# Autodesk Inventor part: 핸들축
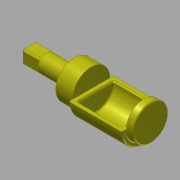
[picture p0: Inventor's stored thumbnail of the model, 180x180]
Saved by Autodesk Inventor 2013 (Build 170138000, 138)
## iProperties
Created: 2018-01
Part Number: 핸들축
Material: 강철, 연강
Document SubType Name: Modeling
Designer: mduedu
Density: 1 g/cm^3
Author: mduedu
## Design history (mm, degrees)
sketch "스케치1"
  geometry: L1 (0, 0)-(-38, 0); L2 (-38, 0)-(-38, -7.5); L3 (-38, -7.5)-(0, -7.5); L4 (0, -7.5)-(0, 0); L5 (-38, 0)-(-53, 0); L6 (-53, 0)-(-53, -16); L7 (-53, -16)-(-38, -16); L8 (-38, -16)-(-38, 0); L9 (-53, 0)-(-98, 0); L10 (-98, 0)-(-98, -19); L11 (-98, -19)-(-53, -19); L12 (-53, -19)-(-53, 0); L13 (-98, 0)-(-104, 0); L14 (-104, 0)-(-104, -15); L15 (-104, -15)-(-98, -15); L16 (-98, -15)-(-98, 0)
  constraints: 32 end point, 8 parallel, 4 horizontal, 4 perpendicular
  dimensions: "d0" = 6 distance of L14.end L15.end; "d2" = 30 diameter of L15 L13; "d3" = 32 diameter of L7 L5; "d4" = 15 distance of L6.end L7.end; "d5" = 45 distance of L10.end L11.end; "d6" = 38 diameter of L11 L9; "d7" = 38 distance of L2.end L3.end; "d8" = 15 diameter of L3 L1
revolve "회전1" sketch "스케치1" stored, may be unused: angle "d9" = 90 deg
sketch "스케치2"
  geometry: L1 (0, -7.5)-(0, 7.5) reference; L2 (0, 7.5)-(38, 7.5) reference; L3 (38, 7.5)-(38, 16) reference; L4 (38, 16)-(53, 16) reference; L5 (53, 16)-(53, 19) reference; L6 (53, 19)-(98, 19) reference; L7 (98, 19)-(98, 15) reference; L8 (98, 15)-(104, 15) reference; L9 (104, 15)-(104, -15) reference; L10 (104, -15)-(98, -15) reference; L11 (98, -15)-(98, -19) reference; L12 (98, -19)-(53, -19) reference; L13 (53, -19)-(53, -16) reference; L14 (53, -16)-(38, -16) reference; L15 (38, -16)-(38, -7.5) reference; L16 (38, -7.5)-(0, -7.5) reference; L17 (0, 0)-(104, 0); L18 (53, 19)-(53, 0); L19 (98, 19)-(98, 0); L20 (98, 0)-(53, 0); L21 (98, 19)-(53, 19)
  constraints: 10 end point, 3 perpendicular, 2 point on line, 1 midpoint, 1 parallel
extrude "돌출1" cut sketch "스케치2" stored distance "d10" = 10; taper "d11" = 0 deg
sketch "스케치3"
  geometry: L1 (45, 0)-(0, 0) reference; L2 (45, 4)-(45, 0) reference; L3 (45, 34)-(45, 4) reference; L4 (45, 38)-(45, 34) reference; L5 (0, 38)-(45, 38) reference; L6 (0, 35)-(0, 38) reference; L7 (0, 35)-(0, 3) reference; L8 (0, 0)-(0, 3) reference; L9 (0, 19)-(45, 19); L10 (4, 19)-(41, 19); L11 (41, 19)-(41, 34); L12 (41, 34)-(4, 34); L13 (4, 34)-(4, 19); 1 further point
  constraints: 10 end point, 2 midpoint, 2 parallel, 1 horizontal, 1 perpendicular, 1 point on line
  dimensions: "d12" = 4 distance between parallel lines of L3 L11; "d13" = 4 distance between parallel lines of L7 L13; "d14" = 4 distance between parallel lines of L12 L5
revolve "회전2" sketch "스케치3" stored, may be unused: angle "d15" = 90 deg
fillet "모깎기1" dims "d16" = 1
chamfer "모따기1" distance "d17" = 1; stored, may be unused: second distance "d18" = 2, angle "d19" = 45 deg
sketch "스케치4"
  geometry: L1 (-6, -6)-(-4.5, -6); L2 (6, -6)-(6, -4.5); L3 (6, 6)-(4.5, 6); L4 (-6, 6)-(-6, 4.5); L5 (-6, -6)-(6, 6); L6 (6, -6)-(-6, 6); L7 (-4.5, 6)-(-6, 6); L8 (-6, 4.5)-(-6, -4.5); L9 (-6, -4.5)-(-6, -6); L10 (-4.5, -6)-(4.5, -6); L11 (4.5, -6)-(6, -6); L12 (6, -4.5)-(6, 4.5); L13 (6, 4.5)-(6, 6); L14 (4.5, 6)-(-4.5, 6); C1 r 7.5 at (0, 0) reference; 2 further points
  constraints: 28 end point, 18 parallel, 9 perpendicular, 3 horizontal, 2 midpoint, 1 coincident, 11 other
  dimensions: "d20" = 12 distance of L4.start L3.start; "d21" = 12 distance of L3.start L2.start (= d20)
extrude "돌출2" cut sketch "스케치4" distance "d22" = 15; taper "d23" = 0 deg
chamfer "모따기2" distance "d24" = 1; stored, may be unused: second distance "d25" = 2, angle "d26" = 45 deg
sketch "스케치5"
  geometry: 2 further points
  constraints: 1 coincident
hole "구멍1" sketch "스케치5" at (5, 4.153) diameter "d27" = 2.459; stored, may be unused: countersink angle "d31" = 90 deg, drill point angle "d33" = 120 deg; dims "d28" = 6.9, "d29" = 4, "d30" = 2, "d32" = 8.4
node "솔리드1"
node "투영된 루프1"
node "절단 모서리 투영1"
